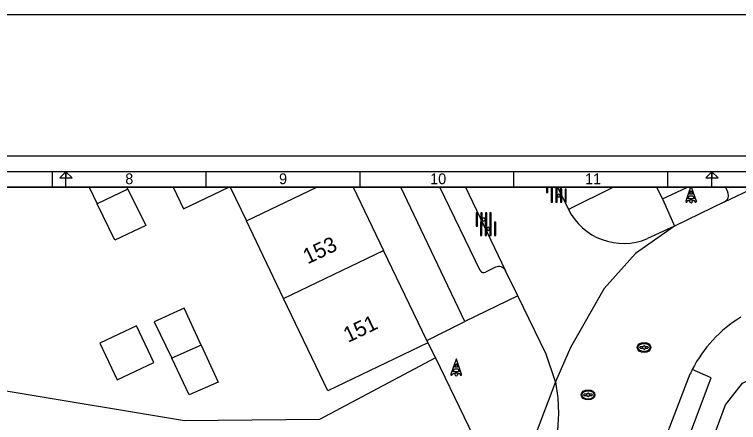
# Model space of a CAD drawing. Extents: x 192664 to 192925, y 446334 to 446521.
# Drawn here: x 192738.2 to 192785.27, y 446494.45 to 446520.97 of the extents above; entities that cross this region are included whole.
import ezdxf

# ---------------------------------------------------------------- set-up
doc = ezdxf.new("R2010")
doc.units = 0
for name, color, linetype in [('( Toegevoegd 29-11-2021 14_41_42) wegdeel vlak', 7, 'Continuous'), ('1010 viewport', 7, 'Continuous'), ('bovenleidingmast', 7, 'Continuous'), ('huisnummerreeks BGT', 7, 'Continuous'), ('inspectie-   rioolput', 7, 'Continuous'), ('kant open verharding', 7, 'Continuous'), ('kant verharding', 7, 'Continuous'), ('kolk', 7, 'Continuous'), ('pand op maaiveld vlak', 7, 'Continuous'), ('verkeerseiland - berm', 7, 'Continuous'), ('X-XX-AL-TEKENBLAD-S', 7, 'Continuous'), ('X-XX-AL-TEKENBLAD_KADER-G', 7, 'Continuous')]:
    doc.layers.add(name, color=color, linetype=linetype)

msp = doc.modelspace()

# ---------------------------------------------------------------- linework, layer by layer
at = {"layer": '( Toegevoegd 29-11-2021 14_41_42) wegdeel vlak'}
msp.add_lwpolyline([(192765.561, 446498.667), (192758.023, 446494.654), (192749.243, 446494.562), (192737.517, 446496.509), (192736.353, 446498.833), (192734.578, 446497.242), (192732.701, 446497.637), (192731.791, 446499.455)], dxfattribs=at)
at = {"layer": '1010 viewport'}
msp.add_lwpolyline([(192675.743, 446509.756), (192860.643, 446509.756), (192860.643, 446345.556), (192675.743, 446345.556)], close=True, dxfattribs=at)
at = {"layer": 'bovenleidingmast'}
for p, q in [((192766.908, 446498.564), (192766.567, 446497.591)), ((192767.267, 446497.591), (192766.926, 446498.564))]:
    msp.add_line(p, q, dxfattribs=at)
for points in [[(192782.533, 446508.838), (192782.212, 446509.756), (192782.154, 446509.756), (192781.833, 446508.838)], [(192782.192, 446509.508), (192782.27, 446509.288), (192782.096, 446509.288), (192782.174, 446509.508)], [(192781.927, 446508.805), (192781.956, 446508.888), (192782.096, 446508.888)], [(192782.27, 446508.888), (192782.41, 446508.888), (192782.439, 446508.805)], [(192766.926, 446498.261), (192767.004, 446498.041), (192766.83, 446498.041), (192766.908, 446498.261)], [(192766.661, 446497.558), (192766.69, 446497.641), (192766.83, 446497.641)], [(192767.004, 446497.641), (192767.144, 446497.641), (192767.173, 446497.558)]]:
    msp.add_lwpolyline(points, dxfattribs=at)
for points in [[(192782.305, 446509.188), (192782.375, 446508.988), (192781.991, 446508.988), (192782.061, 446509.188)], [(192767.039, 446497.941), (192767.109, 446497.741), (192766.725, 446497.741), (192766.795, 446497.941)]]:
    msp.add_lwpolyline(points, close=True, dxfattribs=at)
for centre, radius, start, end in [((192782.183, 446509.505), 0.01, 19.29, 160.71), ((192781.88, 446508.821), 0.05, 160.71, 340.71), ((192782.183, 446508.838), 0.1, 0, 180), ((192782.183, 446508.838), 0.1, 180, 0), ((192782.183, 446508.838), 0.1, 30, 150), ((192782.486, 446508.821), 0.05, 199.29, 19.29), ((192766.917, 446498.561), 0.01, 19.29, 160.71), ((192766.917, 446498.258), 0.01, 19.29, 160.71), ((192766.614, 446497.574), 0.05, 160.71, 340.71), ((192766.917, 446497.591), 0.1, 0, 180), ((192766.917, 446497.591), 0.1, 180, 0), ((192766.917, 446497.591), 0.1, 30, 150), ((192767.22, 446497.574), 0.05, 199.29, 19.29)]:
    msp.add_arc(centre, radius, start, end, dxfattribs=at)
at = {"layer": 'inspectie-   rioolput'}
for p, q in [((192779.033, 446499.367), (192778.876, 446499.367)), ((192778.876, 446499.292), (192779.033, 446499.292)), ((192779.376, 446499.367), (192779.219, 446499.367)), ((192779.219, 446499.292), (192779.376, 446499.292)), ((192775.395, 446496.29), (192775.238, 446496.29)), ((192775.238, 446496.215), (192775.395, 446496.215)), ((192775.738, 446496.29), (192775.581, 446496.29)), ((192775.581, 446496.215), (192775.738, 446496.215))]:
    msp.add_line(p, q, dxfattribs=at)
for centre, radius, start, end in [((192779.126, 446499.33), 0.1, 0, 180), ((192778.876, 446499.33), 0.0375, 90, 270), ((192779.126, 446499.33), 0.1, 157.9757, 180), ((192779.126, 446499.33), 0.1, 180, 202.0243), ((192779.126, 446499.33), 0.1, 180, 0), ((192779.126, 446499.33), 0.1, 0, 22.0243), ((192779.126, 446499.33), 0.1, 337.9757, 0), ((192779.376, 446499.33), 0.0375, 270, 90), ((192775.238, 446496.252), 0.0375, 90, 270), ((192775.488, 446496.252), 0.1, 0, 180), ((192775.488, 446496.252), 0.1, 157.9757, 180), ((192775.488, 446496.252), 0.1, 180, 202.0243), ((192775.488, 446496.252), 0.1, 180, 0), ((192775.488, 446496.252), 0.1, 0, 22.0243), ((192775.488, 446496.252), 0.1, 337.9757, 0), ((192775.738, 446496.252), 0.0375, 270, 90)]:
    msp.add_arc(centre, radius, start, end, dxfattribs=at)
for centre, major_axis, ratio in [((192779.126, 446499.33), (-0.442, 0), 0.73911), ((192779.126, 446499.33), (-0.392, 0), 0.689655), ((192775.488, 446496.252), (-0.442, 0), 0.73911), ((192775.488, 446496.252), (-0.392, 0), 0.689655)]:
    msp.add_ellipse(centre, major_axis=major_axis, ratio=ratio, dxfattribs=at)
at = {"layer": 'kant open verharding'}
for p, q in [((192767.483, 446501.015), (192763.311, 446509.756)), ((192780.331, 446508.982), (192779.967, 446509.756)), ((192770.917, 446502.682), (192770.122, 446504.32)), ((192770.917, 446502.682), (192767.483, 446501.015)), ((192764.996, 446499.775), (192767.483, 446501.015)), ((192765.063, 446499.636), (192765.561, 446498.667))]:
    msp.add_line(p, q, dxfattribs=at)
for points in [[(192779.53, 446482.124), (192780.051, 446483.746), (192784.415, 446495.597), (192785.528, 446497.018), (192791.864, 446500), (192801.451, 446504.762), (192802.996, 446505.531), (192810.052, 446508.944)], [(192781.115, 446507.223), (192778.58, 446505.448), (192776.532, 446503.157), (192774.342, 446499.324), (192773.367, 446497.097)], [(192773.367, 446497.097), (192772.756, 446498.895), (192770.917, 446502.682)], [(192765.561, 446498.667), (192769.255, 446491.03), (192768.995, 446490.291)]]:
    msp.add_lwpolyline(points, dxfattribs=at)
for centre, radius, start, end in [((192777.798, 446510.118), 4.023, 206.7487, 292.6943), ((192789.771, 446494.09), 8.418, 121.1838, 153.1361)]:
    msp.add_arc(centre, radius, start, end, dxfattribs=at)
at = {"layer": 'kant verharding'}
for p, q in [((192768.466, 446504.33), (192765.861, 446509.756)), ((192767.511, 446509.756), (192770.122, 446504.32)), ((192784.351, 446508.796), (192786.378, 446509.756)), ((192781.115, 446507.223), (192779.35, 446506.406)), ((192769.48, 446504.551), (192768.83, 446504.229))]:
    msp.add_line(p, q, dxfattribs=at)
for centre, radius, start, end in [((192769.681, 446504.102), 0.492, 26.3279, 114.0934), ((192768.702, 446504.475), 0.277, 211.574, 297.4102)]:
    msp.add_arc(centre, radius, start, end, dxfattribs=at)
at = {"layer": 'kolk'}
msp.add_line((192773.345, 446509.756), (192773.215, 446509.756), dxfattribs=at)
for points in [[(192772.876, 446509.756), (192772.791, 446509.756), (192772.791, 446509.407), (192772.876, 446509.407)], [(192773.174, 446509.756), (192773.089, 446509.756), (192773.089, 446509.407), (192773.174, 446509.407)], [(192773.471, 446509.756), (192773.386, 446509.756), (192773.386, 446509.407), (192773.471, 446509.407)], [(192773.769, 446509.756), (192773.684, 446509.756), (192773.684, 446509.407), (192773.769, 446509.407)], [(192773.181, 446509.19), (192773.181, 446509.615), (192773.096, 446509.615), (192773.096, 446509.19), (192773.096, 446508.765), (192773.181, 446508.765)], [(192773.479, 446509.19), (192773.479, 446509.615), (192773.394, 446509.615), (192773.394, 446509.19), (192773.394, 446508.765), (192773.479, 446508.765)], [(192773.776, 446509.19), (192773.776, 446509.615), (192773.691, 446509.615), (192773.691, 446509.19), (192773.691, 446508.765), (192773.776, 446508.765)], [(192774.074, 446509.19), (192774.074, 446509.615), (192773.989, 446509.615), (192773.989, 446509.19), (192773.989, 446508.765), (192774.074, 446508.765)], [(192768.302, 446507.647), (192768.302, 446508.072), (192768.217, 446508.072), (192768.217, 446507.647), (192768.217, 446507.222), (192768.302, 446507.222)], [(192768.6, 446507.647), (192768.6, 446508.072), (192768.515, 446508.072), (192768.515, 446507.647), (192768.515, 446507.222), (192768.6, 446507.222)], [(192768.897, 446507.647), (192768.897, 446508.072), (192768.812, 446508.072), (192768.812, 446507.647), (192768.812, 446507.222), (192768.897, 446507.222)], [(192769.195, 446507.647), (192769.195, 446508.072), (192769.11, 446508.072), (192769.11, 446507.647), (192769.11, 446507.222), (192769.195, 446507.222)], [(192768.59, 446507.041), (192768.59, 446507.466), (192768.505, 446507.466), (192768.505, 446507.041), (192768.505, 446506.616), (192768.59, 446506.616)], [(192768.888, 446507.041), (192768.888, 446507.466), (192768.803, 446507.466), (192768.803, 446507.041), (192768.803, 446506.616), (192768.888, 446506.616)], [(192769.185, 446507.041), (192769.185, 446507.466), (192769.1, 446507.466), (192769.1, 446507.041), (192769.1, 446506.616), (192769.185, 446506.616)], [(192769.483, 446507.041), (192769.483, 446507.466), (192769.398, 446507.466), (192769.398, 446507.041), (192769.398, 446506.616), (192769.483, 446506.616)]]:
    msp.add_lwpolyline(points, close=True, dxfattribs=at)
for centre, start, end in [((192773.28, 446509.832), 229.7441, 310.2559), ((192773.585, 446509.19), 0, 180), ((192773.585, 446509.19), 180, 0), ((192768.706, 446507.647), 0, 180), ((192768.706, 446507.647), 180, 0), ((192768.994, 446507.041), 0, 180), ((192768.994, 446507.041), 180, 0)]:
    msp.add_arc(centre, 0.1, start, end, dxfattribs=at)
at = {"layer": 'pand op maaiveld vlak'}
for p, q in [((192743.058, 446509.756), (192743.579, 446508.676)), ((192745.557, 446509.631), (192745.495, 446509.756)), ((192752.22, 446509.756), (192753.275, 446507.558)), ((192753.275, 446507.558), (192757.855, 446509.756)), ((192760.207, 446509.756), (192762.189, 446505.624)), ((192745.557, 446509.631), (192743.579, 446508.676)), ((192755.698, 446502.509), (192753.275, 446507.558)), ((192755.698, 446502.509), (192762.189, 446505.624)), ((192764.996, 446499.775), (192762.189, 446505.624)), ((192750.328, 446499.483), (192748.417, 446498.632)), ((192764.996, 446499.775), (192765.063, 446499.636))]:
    msp.add_line(p, q, dxfattribs=at)
for points in [[(192748.511, 446509.756), (192749.19, 446508.34), (192752.14, 446509.756)], [(192745.557, 446509.631), (192746.733, 446507.266), (192744.722, 446506.306), (192743.579, 446508.676)], [(192765.063, 446499.636), (192758.571, 446496.521), (192755.698, 446502.509)], [(192750.328, 446499.483), (192749.221, 446501.884), (192747.277, 446501.007), (192748.417, 446498.632)], [(192743.745, 446499.601), (192744.873, 446497.221), (192747.254, 446498.35), (192746.127, 446500.729), (192743.745, 446499.601)], [(192750.328, 446499.483), (192751.436, 446497.081), (192749.558, 446496.256), (192748.417, 446498.632)]]:
    msp.add_lwpolyline(points, dxfattribs=at)
at = {"layer": 'verkeerseiland - berm'}
for p, q in [((192773.502, 446509.756), (192774.205, 446508.307)), ((192777.138, 446509.756), (192774.205, 446508.307)), ((192780.331, 446508.982), (192781.945, 446509.756)), ((192784.417, 446509.756), (192784.578, 446509.413)), ((192784.351, 446508.796), (192781.115, 446507.223)), ((192779.096, 446489.802), (192782.127, 446497.618))]:
    msp.add_line(p, q, dxfattribs=at)
for points in [[(192780.331, 446508.982), (192780.745, 446508.054), (192781.115, 446507.223)], [(192780.204, 446488.916), (192780.3, 446488.879), (192783.494, 446497.368), (192782.261, 446497.894)], [(192773.367, 446497.097), (192771.694, 446492.7), (192769.851, 446487.804), (192770.692, 446487.472)], [(192773.367, 446497.097), (192773.526, 446496.058), (192773.566, 446495.048), (192773.494, 446493.942), (192773.307, 446493.007), (192770.985, 446486.905)]]:
    msp.add_lwpolyline(points, dxfattribs=at)
for centre, radius, start, end in [((192784.136, 446509.225), 0.48, 296.6196, 22.9823), ((192793.96, 446492.044), 13.08, 153.4311, 154.7751)]:
    msp.add_arc(centre, radius, start, end, dxfattribs=at)
at = {"layer": 'X-XX-AL-TEKENBLAD-S'}
for p, q in [((192909.543, 446511.756), (192671.743, 446511.756)), ((192908.543, 446510.756), (192674.743, 446510.756)), ((192740.643, 446510.756), (192740.643, 446509.756)), ((192741.543, 446509.756), (192741.543, 446510.756)), ((192750.643, 446510.756), (192750.643, 446509.756)), ((192760.643, 446510.756), (192760.643, 446509.756)), ((192770.643, 446510.756), (192770.643, 446509.756)), ((192780.643, 446510.756), (192780.643, 446509.756)), ((192783.543, 446509.756), (192783.543, 446510.756))]:
    msp.add_line(p, q, dxfattribs=at)
for points in [[(192741.543, 446510.356), (192741.543, 446510.756), (192741.143, 446510.356), (192741.543, 446510.356)], [(192741.543, 446510.756), (192741.543, 446510.356), (192741.943, 446510.356), (192741.543, 446510.756)], [(192783.543, 446510.356), (192783.543, 446510.756), (192783.143, 446510.356), (192783.543, 446510.356)], [(192783.543, 446510.756), (192783.543, 446510.356), (192783.943, 446510.356), (192783.543, 446510.756)]]:
    msp.add_lwpolyline(points, dxfattribs=at)
msp.add_lwpolyline([(192675.743, 446345.556), (192907.543, 446345.556), (192907.543, 446509.756), (192675.743, 446509.756)], close=True, dxfattribs=at)
at = {"layer": 'X-XX-AL-TEKENBLAD_KADER-G'}
msp.add_lwpolyline([(192664.22, 446520.974), (192925.029, 446520.974), (192925.029, 446333.894), (192664.22, 446333.894)], close=True, dxfattribs=at)

# ---------------------------------------------------------------- texts
at = {"layer": 'huisnummerreeks BGT'}
for s, p in [('153', (192757.254, 446504.724)), ('151', (192759.881, 446499.624))]:
    msp.add_text(s, height=1, rotation=25.6, dxfattribs=at).set_placement(p)
at = {"layer": 'X-XX-AL-TEKENBLAD-S'}
for s, p in [('8', (192745.399, 446509.945)), ('9', (192755.399, 446509.945)), ('10', (192765.224, 446509.945)), ('11', (192775.293, 446509.945))]:
    msp.add_text(s, height=0.7, dxfattribs=at).set_placement(p)

doc.saveas('drawing.dxf')
